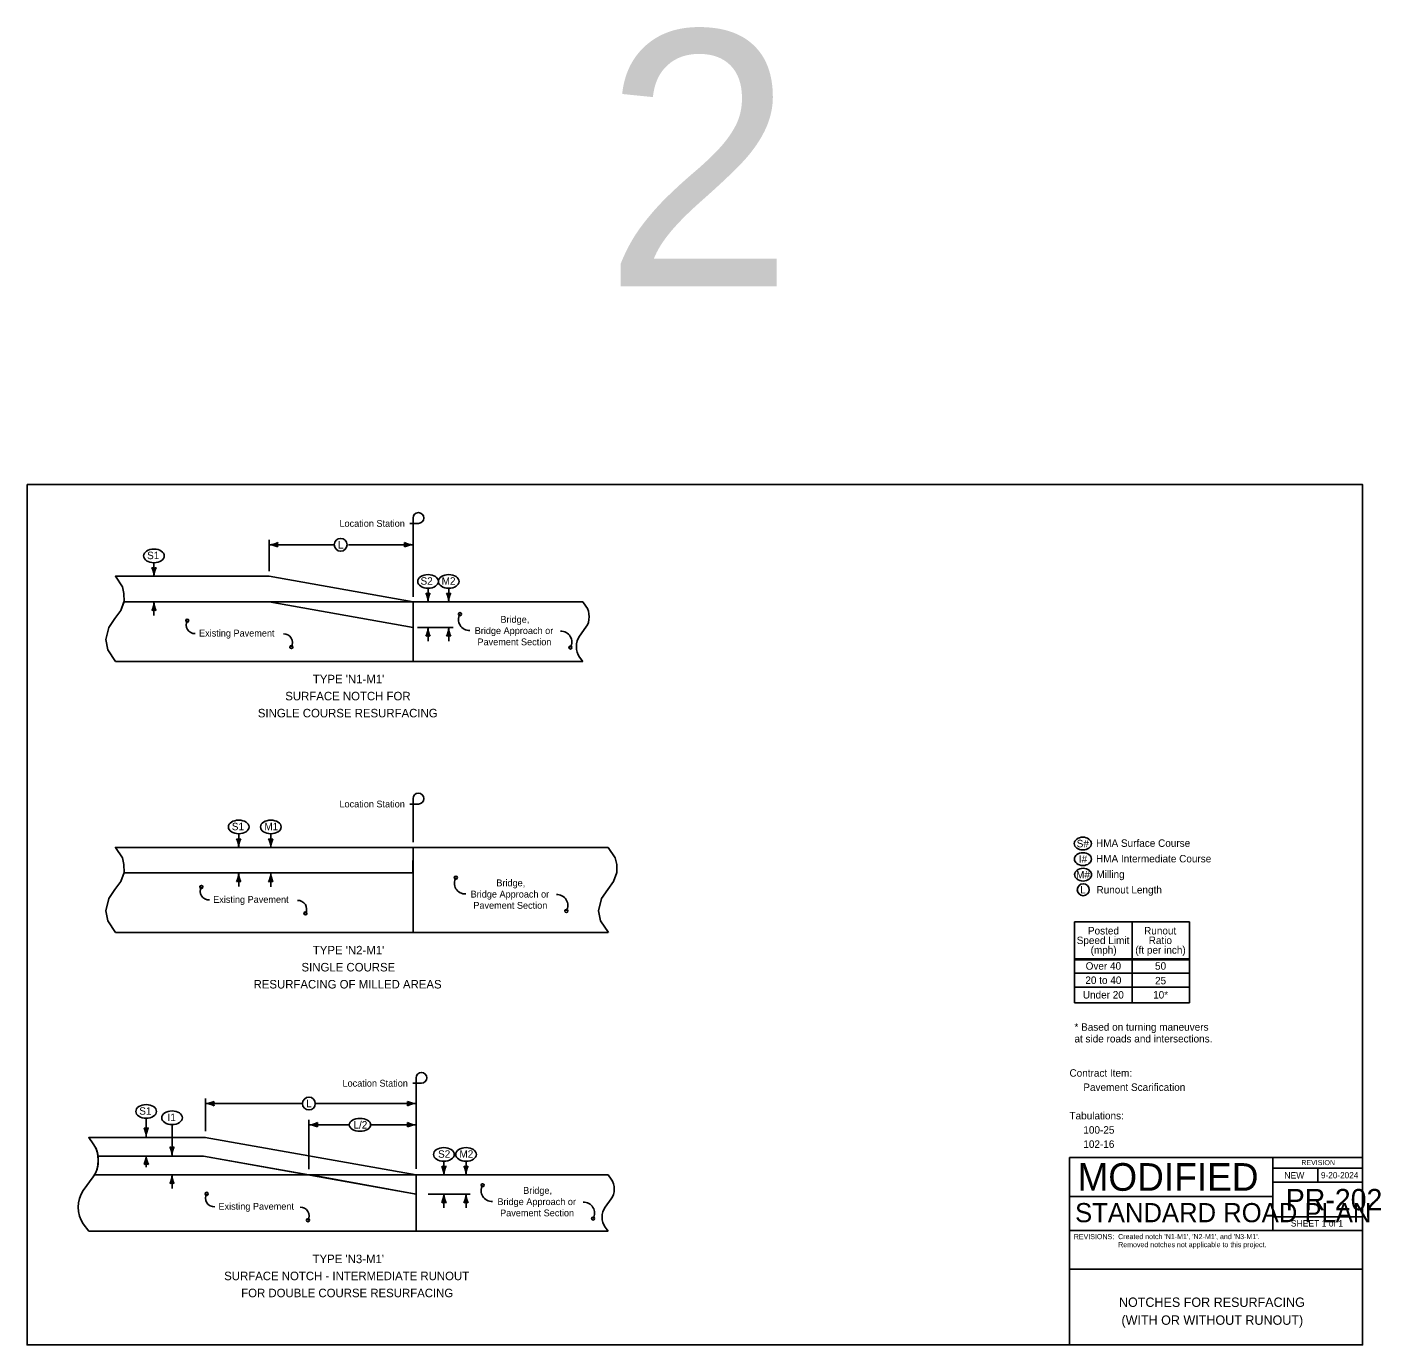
# Model space of a CAD drawing. Extents: x 10133 to 81668, y 2218 to 11018.
# Drawn here: x 13733 to 16911, y 7924 to 11018 of the extents above; entities that cross this region are included whole.
import ezdxf

# ---------------------------------------------------------------- set-up
doc = ezdxf.new("R2010")
doc.units = 0
for name, color, linetype in [('Default', 7, 'Continuous'), ('dsnNonPlotable', 7, 'Continuous'), ('dsnShtPlotShapeBatchPrint', 7, 'Continuous'), ('dsnStdBlock', 7, 'Continuous'), ('dsnStdBlockModified', 7, 'Continuous'), ('dsnStdBlockNotModified', 7, 'Continuous'), ('dsnStdBorder', 7, 'Continuous'), ('Level 2', 7, 'Continuous'), ('SheetBorder', 7, 'Continuous'), ('SheetText', 7, 'Continuous')]:
    doc.layers.add(name, color=color, linetype=linetype)

msp = doc.modelspace()

# ---------------------------------------------------------------- linework, layer by layer
at = {"layer": 'Default'}
for points in [[(13952.3, 9648.6), (13960.1, 9669.5), (13959.8, 9688.6), (13956.4, 9704), (13939.8, 9728.6), (14301, 9728.6), (14638.5, 9668.6), (14638.5, 9608.6), (14301, 9668.6), (13959.3, 9668.6)], [(13960.1, 9033), (13959.8, 9052.1), (13956.4, 9067.5), (13939.8, 9092.1), (14301, 9092.1), (14638.5, 9092.1), (14638.4, 9032.1), (14301, 9032.1), (13959.7, 9032.1)]]:
    msp.add_lwpolyline(points, close=True, dxfattribs=at)
for points in [[(13887.9, 8396.3), (13877.1, 8411), (14150.6, 8411), (14645.6, 8323), (14394.2, 8323), (14146.7, 8367), (13899, 8367)], [(14396.4, 8322.6), (14645.6, 8278.3), (14645.6, 8323), (14396.7, 8323), (14396.4, 8322.6)]]:
    msp.add_lwpolyline(points, dxfattribs=at)
msp.add_ellipse((13859.4, 8357.4), major_axis=(0, -55), ratio=0.732645, start_param=1.746494, end_param=2.356194, dxfattribs=at)
at = {"layer": 'dsnNonPlotable'}
msp.add_lwpolyline([(13899, 8367), (14146.7, 8367), (14394.2, 8323), (13890.8, 8323)], dxfattribs=at)
msp.add_ellipse((13859.4, 8357.4), major_axis=(0, -55), ratio=0.732645, start_param=0.895403, end_param=1.746494, dxfattribs=at)
at = {"layer": 'dsnStdBlock'}
for p, q in [((14651.2, 9852.8), (14630.8, 9852.8)), ((14638.5, 9845.2), (14638.5, 9865.5)), ((14638.5, 9845.2), (14638.5, 9680.6)), ((14301, 9814.6), (14301, 9740.6)), ((14301, 9802.6), (14452.2, 9802.6)), ((14487.2, 9802.6), (14638.5, 9802.6)), ((14030.4, 9760.6), (14030.4, 9728.6)), ((13939.8, 9728.6), (14301, 9728.6)), ((14638.5, 9668.6), (14301, 9728.6)), ((14673.8, 9700.6), (14673.8, 9668.6)), ((14722.3, 9700.6), (14722.3, 9668.6)), ((14301, 9668.6), (13959.3, 9668.6)), ((13959.4, 9668.6), (14301, 9668.6)), ((14030.4, 9668.6), (14030.4, 9636.6)), ((14638.5, 9608.6), (14301, 9668.6)), ((14638.5, 9668.6), (14638.5, 9528.6)), ((14638.5, 9668.6), (15037, 9668.6)), ((14638.5, 9668.6), (14638.5, 9528.6)), ((15037, 9668.6), (15044.5, 9658.4)), ((14648.7, 9608.6), (14732.8, 9608.6)), ((14673.8, 9608.6), (14673.8, 9576.6)), ((14722.3, 9608.6), (14722.3, 9576.6)), ((15044.5, 9608.9), (15029.5, 9588.4)), ((15029.5, 9538.9), (15037, 9528.6)), ((13939.8, 9528.6), (15037, 9528.6)), ((14651.2, 9194), (14630.8, 9194)), ((14638.5, 9186.4), (14638.5, 9206.7)), ((14638.5, 9186.4), (14638.5, 9104.1)), ((14229.3, 9124.1), (14229.3, 9092.1)), ((14304.7, 9124.1), (14304.7, 9092.1)), ((13939.8, 9092.1), (14301, 9092.1)), ((14638.5, 9092.1), (14301, 9092.1)), ((14638.5, 9092.1), (14638.5, 8892.1)), ((14638.5, 9092.1), (15096.6, 9092.1)), ((14638.5, 9092.1), (14638.5, 8892.1)), ((14638.5, 9032.1), (13959.7, 9032.1)), ((14229.3, 9032.1), (14229.3, 9000.1)), ((14304.7, 9031.6), (14304.7, 8999.6)), ((16191.1, 8917.1), (16191.1, 8726.9)), ((16191.1, 8917.1), (16461.5, 8917.1)), ((16326.3, 8917.1), (16326.3, 8726.9)), ((16461.5, 8917.1), (16461.5, 8726.9)), ((13939.8, 8892.1), (15096.6, 8892.1)), ((16191.1, 8830.8), (16461.5, 8830.8)), ((16191.1, 8827.8), (16461.5, 8827.8)), ((16191.1, 8796.6), (16461.5, 8796.6)), ((16191.1, 8764.2), (16461.5, 8764.2)), ((16191.1, 8726.9), (16461.5, 8726.9)), ((14645.6, 8530.8), (14645.6, 8551.1)), ((14658.3, 8538.4), (14638, 8538.4)), ((14645.6, 8530.8), (14645.6, 8337.3)), ((14151.1, 8502.8), (14151.1, 8425.9)), ((14151.1, 8490.8), (14379, 8490.8)), ((14409, 8490.8), (14645.6, 8490.8)), ((14012.1, 8456.3), (14012.1, 8413.3)), ((14072.8, 8441.3), (14072.8, 8368.3)), ((14394.2, 8452.8), (14394.2, 8336.5)), ((14488.9, 8440.8), (14394.2, 8440.8)), ((14538.9, 8440.8), (14645.6, 8440.8)), ((13877.1, 8411), (13887.9, 8396.3)), ((14151.1, 8410.9), (13877.1, 8411)), ((14645.6, 8323), (14150.6, 8411)), ((13899, 8367), (14146.7, 8367)), ((14012.1, 8368.3), (14012.1, 8341.6)), ((14645.6, 8278.3), (14146.7, 8367)), ((14710.9, 8355.3), (14710.9, 8323.3)), ((14763, 8355.3), (14763, 8323.3)), ((13887.9, 8318.5), (13864.3, 8286.3)), ((13890.8, 8323), (14645.6, 8323)), ((14072.8, 8323.3), (14072.8, 8291.3)), ((14394.2, 8323), (14394.2, 8323)), ((14394.2, 8323), (14645.6, 8323)), ((14645.6, 8323), (15096.6, 8323)), ((14645.6, 8323), (14645.6, 8278.3)), ((15096.6, 8323), (15103.7, 8313.3)), ((14645.6, 8278.3), (14645.6, 8191)), ((14674.4, 8278.3), (14772.5, 8278.3)), ((14710.9, 8278.3), (14710.9, 8246.2)), ((14763, 8278.3), (14763, 8246.2)), ((15103.7, 8266.7), (15089.5, 8247.3)), ((13864.3, 8208.5), (13877.5, 8191)), ((15089.5, 8200.7), (15096.6, 8191)), ((13877.5, 8191), (15096.6, 8191))]:
    msp.add_line(p, q, dxfattribs=at)
for points in [[(13939.8, 9728.6), (13956.4, 9704), (13959.8, 9688.6), (13960.1, 9669.5), (13952.3, 9648.6), (13938.9, 9629.9), (13924.1, 9608.6), (13917.4, 9579.9), (13921.9, 9556), (13940.2, 9528.6)], [(13939.8, 9092.1), (13956.4, 9067.5), (13959.8, 9052.1), (13960.1, 9033), (13952.3, 9012.1), (13938.9, 8993.4), (13924.1, 8972.1), (13917.4, 8943.4), (13921.9, 8919.5), (13940.2, 8892.1)], [(15096.6, 9092.1), (15113.2, 9067.5), (15116.6, 9052.1), (15116.8, 9033), (15109.1, 9012.1), (15095.7, 8993.4), (15080.9, 8972.1), (15074.2, 8943.4), (15078.7, 8919.5), (15097, 8892.1)]]:
    msp.add_lwpolyline(points, dxfattribs=at)
for points in [[(14301, 9668.6), (14638.5, 9608.6), (14638.5, 9668.6)], [(14638.5, 9092.1), (14638.5, 9032.1), (14301, 9032.1), (13959.7, 9032.1), (13960.1, 9033), (13959.8, 9052.1), (13956.4, 9067.5), (13939.8, 9092.1), (14301, 9092.1)], [(14645.6, 8278.3), (14398.1, 8323), (14645.6, 8323)]]:
    msp.add_lwpolyline(points, close=True, dxfattribs=at)
for centre, radius in [((14468.7, 9802.6), 15), ((14748.6, 9639.7), 3.56), ((14108.5, 9624.6), 3.56), ((14352.9, 9562.6), 3.56), ((15008, 9561.5), 3.56), ((14141.6, 8999.3), 3.56), ((14739, 9021.1), 3.56), ((16211.8, 8992.7), 14), ((14386, 8937.2), 3.56), ((14998.4, 8942.9), 3.56), ((14394, 8490.8), 15), ((14801.9, 8299), 3.56), ((14154.1, 8278.8), 3.56), ((14391.9, 8216.8), 3.56), ((15061.3, 8220.8), 3.56)]:
    msp.add_circle(centre, radius, dxfattribs=at)
for centre, radius, start, end in [((14651.2, 9865.5), 12.7, 270, 180), ((14301, 9845.8), 43.2, 270, 298.0725), ((14301, 9759.4), 43.2, 61.9275, 90), ((14337.2, 9802.6), 16.7, 162.2666, 197.7334), ((14602.2, 9802.6), 16.7, 342.2666, 17.7333), ((14638.5, 9845.8), 43.2, 241.9275, 270), ((14638.5, 9759.4), 43.2, 90, 118.0725), ((14030.4, 9764.8), 16.7, 252.2666, 287.7333), ((13987.2, 9728.6), 43.2, 360, 28.0725), ((14073.6, 9728.6), 43.2, 151.9275, 180), ((13987.2, 9668.6), 43.2, 331.9275, 360), ((14073.6, 9668.6), 43.2, 180, 208.0725), ((14673.8, 9704.8), 16.7, 252.2666, 287.7333), ((14630.6, 9668.6), 43.2, 360, 28.0725), ((14716.9, 9668.6), 43.2, 151.9275, 180), ((14722.3, 9704.8), 16.7, 252.2666, 287.7333), ((14679.1, 9668.6), 43.2, 360, 28.0725), ((14765.5, 9668.6), 43.2, 151.9275, 180), ((14030.4, 9632.4), 16.7, 72.2666, 107.7334), ((14770.8, 9626.9), 25.6, 150.0683, 272.8436), ((14126.3, 9614.4), 20.4, 150.0683, 272.8436), ((14630.6, 9608.6), 43.2, 331.9275, 360), ((14716.9, 9608.6), 43.2, 180, 208.0725), ((14679.1, 9608.6), 43.2, 331.9275, 360), ((14765.5, 9608.6), 43.2, 180, 208.0725), ((14985.8, 9574.3), 25.6, 330.0683, 92.8436), ((14335.2, 9572.8), 20.4, 330.0683, 92.8436), ((14673.8, 9572.4), 16.7, 72.2666, 107.7334), ((14722.3, 9572.4), 16.7, 72.2666, 107.7334), ((14651.2, 9206.7), 12.7, 270, 180), ((14229.3, 9128.3), 16.7, 252.2666, 287.7333), ((14186.1, 9092.1), 43.2, 360, 28.0725), ((14272.4, 9092.1), 43.2, 151.9275, 180), ((14304.7, 9128.3), 16.7, 252.2666, 287.7333), ((14261.5, 9092.1), 43.2, 360, 28.0725), ((14347.9, 9092.1), 43.2, 151.9275, 180), ((14186.1, 9032.1), 43.2, 331.9275, 360), ((14272.4, 9032.1), 43.2, 180, 208.0725), ((14261.5, 9031.6), 43.2, 331.9275, 360), ((14347.8, 9031.6), 43.2, 180, 208.0725), ((14159.4, 8989.1), 20.4, 150.0683, 272.8436), ((14229.3, 8995.9), 16.7, 72.2666, 107.7334), ((14304.7, 8995.4), 16.7, 72.2666, 107.7334), ((14761.2, 9008.4), 25.6, 150.0683, 272.8436), ((14368.3, 8947.4), 20.4, 330.0683, 92.8436), ((14976.2, 8955.7), 25.6, 330.0683, 92.8436), ((14658.3, 8551.1), 12.7, 270, 180), ((14151.1, 8534), 43.2, 270, 298.0725), ((14151.1, 8447.6), 43.2, 61.9275, 90), ((14187.4, 8490.8), 16.7, 162.2666, 197.7334), ((14609.4, 8490.8), 16.7, 342.2666, 17.7333), ((14645.6, 8534), 43.2, 241.9275, 270), ((14645.6, 8447.6), 43.2, 90, 118.0725), ((14012.1, 8449.5), 16.7, 252.2666, 287.7333), ((13968.9, 8413.3), 43.2, 360, 28.0725), ((14055.2, 8413.3), 43.2, 151.9275, 180), ((14394.2, 8484), 43.2, 270, 298.0725), ((14394.2, 8397.6), 43.2, 61.9275, 90), ((14430.4, 8440.8), 16.7, 162.2666, 197.7334), ((14609.4, 8440.8), 16.7, 342.2666, 17.7333), ((14645.6, 8484), 43.2, 241.9275, 270), ((14645.6, 8397.6), 43.2, 90, 118.0725), ((13968.9, 8368.3), 43.2, 331.9275, 360), ((14055.3, 8368.3), 43.2, 180, 208.0725), ((14072.8, 8404.5), 16.7, 252.2666, 287.7333), ((14029.6, 8368.3), 43.2, 360, 28.0725), ((14116, 8368.3), 43.2, 151.9275, 180), ((14012.1, 8332.1), 16.7, 72.2666, 107.7334), ((14710.9, 8359.5), 16.7, 252.2666, 287.7333), ((14667.7, 8323.3), 43.2, 360, 28.0725), ((14754.1, 8323.3), 43.2, 151.9275, 180), ((14763, 8359.5), 16.7, 252.2666, 287.7333), ((14719.9, 8323.3), 43.2, 360, 28.0725), ((14806.2, 8323.3), 43.2, 151.9275, 180), ((14029.7, 8323.3), 43.2, 331.9275, 360), ((14072.8, 8287.1), 16.7, 72.2666, 107.7334), ((14116, 8323.3), 43.2, 180, 208.0725), ((14824, 8286.2), 25.6, 150.0683, 272.8436), ((14171.9, 8268.6), 20.4, 150.0683, 272.8436), ((14667.7, 8278.3), 43.2, 331.9275, 360), ((14754.1, 8278.3), 43.2, 180, 208.0725), ((14719.9, 8278.3), 43.2, 331.9275, 360), ((14806.2, 8278.3), 43.2, 180, 208.0725), ((14374.2, 8227), 20.4, 330.0683, 92.8436), ((14710.9, 8242.1), 16.7, 72.2666, 107.7334), ((14763, 8242.1), 16.7, 72.2666, 107.7334), ((15039.1, 8233.5), 25.6, 330.0683, 92.8436)]:
    msp.add_arc(centre, radius, start, end, dxfattribs=at)
for centre, major_axis, ratio in [((14030.4, 9776.6), (-24.3, 0), 0.658717), ((14673.8, 9716.6), (-24.3, 0), 0.658717), ((14722.3, 9716.6), (-24.3, 0), 0.658717), ((14229.3, 9140.1), (-24.3, 0), 0.658717), ((14304.7, 9140.1), (-24.3, 0), 0.658717), ((16210.8, 9101.1), (-20, 0), 0.749963), ((16211.1, 9064.7), (-20, 0), 0.749963), ((16211.4, 9028.2), (-20, 0), 0.749963), ((14012.1, 8472.3), (-24.3, 0), 0.658717), ((14072.8, 8457.3), (-24.3, 0), 0.658717), ((14513.9, 8440.8), (25, 0), 0.6), ((14710.9, 8371.3), (-24.3, 0), 0.658717), ((14763, 8371.3), (-24.3, 0), 0.658717)]:
    msp.add_ellipse(centre, major_axis=major_axis, ratio=ratio, dxfattribs=at)
for centre, major_axis, ratio in [((15026.4, 9633.6), (0, -35), 0.732627), ((15047.6, 9563.6), (0, 35), 0.732627), ((13859.4, 8357.4), (0, -55), 0.732645), ((15086.6, 8290), (0, -33), 0.732645), ((13892.8, 8247.4), (0, 55), 0.732645), ((15106.6, 8224), (0, 33), 0.732645)]:
    msp.add_ellipse(centre, major_axis=major_axis, ratio=ratio, start_param=0.785398, end_param=2.356194, dxfattribs=at)
at = {"layer": 'dsnStdBlockModified'}
for p, q in [((16656.6, 8364), (16656.6, 8272.7)), ((16656.6, 8339.1), (16867.5, 8339.1)), ((16762.1, 8339.1), (16762.1, 8305.9)), ((16656.6, 8305.9), (16867.5, 8305.9)), ((16656.6, 8272.7), (16656.6, 8192.7)), ((16867.5, 8224.9), (16656.6, 8224.9)), ((16179.5, 8192.7), (16867.5, 8192.7))]:
    msp.add_line(p, q, dxfattribs=at)
msp.add_lwpolyline([(16179.5, 8364), (16867.5, 8364), (16867.5, 7924), (16179.5, 7924)], close=True, dxfattribs=at)
at = {"layer": 'dsnStdBorder'}
for p, q in [((16179.5, 8272.7), (16656.6, 8272.7)), ((16179.5, 8101.7), (16867.5, 8101.7))]:
    msp.add_line(p, q, dxfattribs=at)
at = {"layer": 'SheetBorder'}
msp.add_lwpolyline([(13732.5, 9944), (16867.5, 9944), (16867.5, 7924), (13732.5, 7924)], close=True, dxfattribs=at)

# ---------------------------------------------------------------- texts
at = {"layer": 'dsnShtPlotShapeBatchPrint'}
for s, p in [('L', (14387.7, 8482)), ('L/2', (14498.7, 8432))]:
    msp.add_text(s, height=17.5, dxfattribs=at).set_placement(p)
at = {"layer": 'dsnStdBlock'}
for s, p in [('Contract Item:', (16179.5, 8553.8)), ('     Pavement Scarification', (16179.5, 8520.4)), ('Tabulations:', (16179.5, 8453.5)), ('     100-25', (16179.5, 8420.1)), ('     102-16', (16179.5, 8386.7))]:
    msp.add_text(s, height=17.5, dxfattribs=at).set_placement(p)
at = {"layer": 'dsnStdBlockModified'}
for s, height, p in [('REVISION', 12, (16723.6, 8346.2)), ('MODIFIED', 65, (16198.3, 8285.9)), ('NEW', 15, (16683.9, 8314.7)), ('9-20-2024', 14.4, (16769.8, 8315.3)), ('PR-202', 50, (16687.2, 8240.2)), ('STANDARD ROAD PLAN', 45.001, (16192.6, 8212.1)), ('SHEET 1 of 1', 15, (16699, 8202)), ('NOTCHES FOR RESURFACING', 22, (16295.6, 8013.3)), ('(WITH OR WITHOUT RUNOUT)', 22, (16301.5, 7971.3))]:
    msp.add_text(s, height=height, dxfattribs=at).set_placement(p)
at = {"layer": 'dsnStdBlockNotModified'}
for s, height, p in [('Location Station', 16, (14465.8, 9844.8)), ('L', 17.5, (14462.4, 9793.9)), ('S1', 17.5, (14014.3, 9768.9)), ('S2', 17.5, (14656.2, 9708.9)), ('M2', 17.5, (14705.7, 9708.9)), ('Bridge,', 16, (14843.7, 9619.4)), ('Existing Pavement', 16, (14136.2, 9587.2)), ('Bridge Approach or', 16, (14783.3, 9593)), ('Pavement Section', 16, (14789.7, 9566.6)), ("TYPE 'N1-M1'", 20, (14403.3, 9477.4)), ('SURFACE NOTCH FOR', 20, (14338.6, 9437.4)), ('SINGLE COURSE RESURFACING', 20, (14274.2, 9397.4)), ('Location Station', 16, (14465.8, 9186)), ('S1', 17.5, (14213.1, 9132.4)), ('M1', 17.5, (14289.5, 9132.4)), ('S#', 17.5, (16196.4, 9092.4)), ('HMA Surface Course', 17.5, (16241.8, 9093.4)), ('I#', 17.5, (16201.4, 9055.9)), ('HMA Intermediate Course', 17.5, (16241.8, 9056.9)), ('M#', 17.5, (16195.1, 9019.4)), ('Milling', 17.5, (16242.6, 9020.4)), ('Bridge,', 16, (14834.1, 9000.8)), ('L', 17.5, (16204.5, 8983.9)), ('Runout Length', 17.5, (16242.8, 8983.9)), ('Existing Pavement', 16, (14169.3, 8961.9)), ('Bridge Approach or', 16, (14773.7, 8974.4)), ('Pavement Section', 16, (14780.1, 8948)), ('Posted', 17.5, (16222.8, 8887.7)), ('Runout', 17.5, (16354.6, 8887.7)), ('Speed Limit', 17.5, (16196.4, 8865.2)), ('Ratio', 17.5, (16365.4, 8865.2)), ("TYPE 'N2-M1'", 20, (14403.3, 8840.9)), ('(mph)', 17.5, (16229.1, 8842.7)), ('(ft per inch)', 17.5, (16333.9, 8842.7)), ('SINGLE COURSE', 20, (14376.7, 8800.9)), ('Over 40', 17.5, (16217.4, 8805)), ('50', 17.5, (16380.3, 8805)), ('RESURFACING OF MILLED AREAS', 20, (14264.2, 8760.9)), ('20 to 40', 17.5, (16216.7, 8771.6)), ('25', 17.5, (16380.3, 8770.6)), ('Under 20', 17.5, (16210.8, 8737.3)), ('10*', 17.5, (16375.8, 8737.3)), ('* Based on turning maneuvers ', 17.5, (16191.1, 8661.7)), ('at side roads and intersections.', 17.5, (16191.1, 8634.2)), ('Location Station', 16, (14473, 8530.4)), ('S1', 17.5, (13995.9, 8464.5)), ('I1', 17.5, (14062.3, 8449.5)), ('S2', 17.5, (14697.2, 8363.5)), ('M2', 17.5, (14747.4, 8363.5)), ('Bridge,', 16, (14897, 8278.7)), ('Bridge Approach or', 16, (14836.6, 8252.3)), ('Existing Pavement', 16, (14181.8, 8241.4)), ('Pavement Section', 16, (14842.9, 8225.9))]:
    msp.add_text(s, height=height, dxfattribs=at).set_placement(p)
at = {"layer": 'dsnStdBorder'}
for s, p in [('REVISIONS:', (16189.5, 8172.3)), ("Created notch 'N1-M1', 'N2-M1', and 'N3-M1'.", (16293.6, 8172.4)), ('Removed notches not applicable to this project.', (16293.6, 8153.5))]:
    msp.add_text(s, height=12, dxfattribs=at).set_placement(p)
at = {"layer": 'Level 2'}
for s, p in [("TYPE 'N3-M1'", (14402.7, 8116)), ('SURFACE NOTCH - INTERMEDIATE RUNOUT', (14195.2, 8076)), ('FOR DOUBLE COURSE RESURFACING', (14235.1, 8036))]:
    msp.add_text(s, height=20, dxfattribs=at).set_placement(p)
at = {"layer": 'SheetText'}
msp.add_text('2', height=600, dxfattribs=at).set_placement((15085.9, 10409.2))

doc.saveas('drawing.dxf')
